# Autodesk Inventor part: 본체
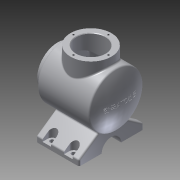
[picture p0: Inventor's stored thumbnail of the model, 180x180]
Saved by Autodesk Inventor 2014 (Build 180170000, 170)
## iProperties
Created: 2017-04
Part Number: 본체
Material: 알루미늄 6061
Document SubType Name: Modeling
Designer: user
Density: 2.71 g/cm^3
Appearance: 알루미늄 - 평지
Mass: 1669.39 g
Surface Area: 1069.84 cm^2
Volume: 616.012 cm^3
Author: user
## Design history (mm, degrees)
sketch "스케치1"
  geometry: L1 (-54, 0)-(54, 0); L2 (-54, 0)-(-54, 50); L3 (-54, 50)-(42.336, 50); A1 r 113 centre (-59, 0) between (54, 0) and (42.336, 50); 2 further points
  constraints: 6 end point, 2 perpendicular, 2 point on circle, 1 centre point, 1 coincident, 1 horizontal, 1 horizontal alignment, 1 midpoint
  dimensions: "d1" = 113 radius of A1; "d2" = 108 distance from line of L1.end L2; "d3" = 100 diameter of L3 L1
revolve "회전1" sketch "스케치1" stored, may be unused: angle "d4" = 90 deg
sketch "스케치2"
  geometry: C1 r 50 at (0, 0) reference; C2 r 38 at (0, 0)
  constraints: 1 centre point, 1 coincident
  dimensions: "d5" = 76 diameter of C2
extrude "돌출1" join sketch "스케치2" distance "d6" = 12; taper "d7" = 0 deg
node "작업 평면1"
sketch "스케치3"
  geometry: L1 (-45.101, 21.584)-(-72, 60); L2 (-72, 60)-(-82, 60); L3 (-82, 60)-(-82, -60); L4 (-82, -60)-(-72, -60); L5 (-72, -60)-(-45.101, -21.584); A1 r 50 centre (0, 0) between (-45.101, 21.584) and (-45.101, -21.584) reference; A2 r 18 centre (-82, 0) between (-82, -18) and (-82, 18); 2 further points
  constraints: 10 end point, 4 point on circle, 2 perpendicular, 2 point on line, 1 centre point, 1 coincident, 1 horizontal, 1 horizontal alignment, 1 midpoint
  dimensions: "d9" = 82 distance from line of point (0, 0) L3; "d10" = 10 distance of L1.end L2.end; "d11" = 10 distance of L3.end L4.end; "d12" = 55 deg angle of L1 L2; "d13" = 55 deg angle of L5 L4; "d14" = 120 distance of L2.end L3.end; "d15" = 36 diameter of A2
extrude "돌출2" join sketch "스케치3" distance "d16" = 80; taper "d17" = 0 deg
node "작업 평면2"
sketch "스케치4"
  geometry: L1 (-8, 10)-(-8, 110) reference; C1 r 38 at (42, 60); 1 further point
  constraints: 1 centre point, 1 horizontal alignment
  dimensions: "d19" = 76 diameter of C1; "d20" = 50 distance from line of C1.centre L1
extrude "돌출3" join sketch "스케치4" stored distance "d21" = 80; taper "d22" = 0 deg
sketch "스케치5"
  geometry: L1 (66, -38)-(66, 38) reference; L2 (66, 0)-(-54, 0); L3 (54, 50)-(-42.336, 50) reference; L4 (54, 50)-(54, -50) reference; L5 (54, 38)-(66, 38) reference; L6 (54, -38)-(66, -38) reference; L7 (54, -50)-(-42.336, -50) reference; L8 (-33.903, 40)-(41, 40); L9 (44, 37)-(44, 27); L10 (44, 27)-(66, 27); A1 r 113 centre (59, 0) between (-42.336, 50) and (-42.336, -50) reference; A2 r 103 centre (59, 0) between (-36.69, 38.11) and (-44, 0); A3 r 3 centre (-33.903, 37) between (-33.903, 40) and (-36.69, 38.11); A4 r 3 centre (41, 37) between (44, 37) and (41, 40); 2 further points
  constraints: 8 end point, 8 point on circle, 4 tangent, 3 centre point, 3 point on line, 1 equal radius, 1 midpoint, 1 perpendicular
  dimensions: "d23" = 10 radial gap between concentric circles of A2 A1; "d24" = 10 distance between parallel lines of L8 L3; "d25" = 80 diameter of L8 L2 (derived); "d26" = 10 distance between parallel lines of L9 L4; "d27" = 54 diameter of L10 L2; "d28" = 3 radius of A3; "d44" = 22 distance of L9.end L10.end (derived)
revolve "회전2" sketch "스케치5" stored, may be unused: angle "d29" = 90 deg
sketch "스케치6"
  geometry: C1 r 38 at (0, 0) reference; C2 r 27 at (0, 0); 1 further point
  constraints: 1 centre point, 1 coincident
  dimensions: "d30" = 54 diameter of C2
extrude "돌출4" cut sketch "스케치6" stored distance "d31" = 80; taper "d32" = 0 deg
sketch "스케치7"
  geometry: C1 r 27 at (0, 0) reference; C2 r 38 at (0, 0) reference; A1 r 32.5 centre (0, 0) between (0, 32.5) and (-32.5, 0); 3 further points
  constraints: 4 point on circle, 2 horizontal alignment, 2 vertical alignment, 1 centre point, 1 coincident
  dimensions: "d33" = 65 diameter of A1
hole "구멍1" sketch "스케치7" at (0, 32.5), (-32.5, 0), (32.5, 0), (0, -32.5) diameter "d34" = 3.242; stored, may be unused: countersink angle "d38" = 90 deg, drill point angle "d40" = 118 deg; dims "d35" = 8, "d36" = 4, "d37" = 2, "d39" = 10
chamfer "모따기1" distance "d41" = 1; stored, may be unused: second distance "d42" = 2, angle "d43" = 45 deg
sketch "스케치8"
  geometry: C1 r 38 at (0, 0) reference; C2 r 28 at (0, 0) reference; A1 r 32.5 centre (0, 0) between (0, 32.5) and (32.5, 0); 2 further points
  constraints: 4 point on circle, 2 horizontal alignment, 2 vertical alignment, 1 centre point, 1 coincident
  dimensions: "d45" = 65 diameter of A1
hole "구멍2" sketch "스케치8" at (0, 32.5), (32.5, 0), (0, -32.5), (-32.5, 0) diameter "d46" = 3.242; stored, may be unused: countersink angle "d50" = 90 deg, drill point angle "d52" = 118 deg; dims "d47" = 8, "d48" = 4, "d49" = 2, "d51" = 10
node "작업 평면3"
sketch "스케치9"
  geometry: L1 (80, 0)-(80, 42) reference; L2 (0, 0)-(80, 0) reference; L3 (12, 10)-(12, 0); L4 (28, 10)-(28, 0); L5 (52, 10)-(52, 0); L6 (68, 10)-(68, 0); A1 r 8 centre (60, 10) between (68, 10) and (52, 10); A2 r 8 centre (20, 10) between (28, 10) and (12, 10); 1 further point
  constraints: 8 end point, 4 point on circle, 4 point on line, 4 tangent, 3 perpendicular, 2 centre point, 1 horizontal alignment, 1 parallel
  dimensions: "d54" = 16 diameter of A1; "d55" = 16 diameter of A2; "d56" = 40 distance of A1.centre A2.centre; "d57" = 20 distance from line of A1.centre L1; "d58" = 10 distance from line of A1.centre L2
extrude "돌출5" cut sketch "스케치9" stored distance "d59" = 80; taper "d60" = 0 deg
hole "구멍3" diameter "d63" = 8; stored, may be unused: countersink angle "d67" = 90 deg, drill point angle "d69" = 118 deg; dims "d61" = 10, "d62" = 10, "d64" = 8, "d65" = 4, "d66" = 2, "d68" = 10
hole "구멍4" diameter "d72" = 8; stored, may be unused: countersink angle "d76" = 90 deg, drill point angle "d78" = 118 deg; dims "d70" = 10, "d71" = 10, "d73" = 8, "d74" = 4, "d75" = 2, "d77" = 10
node "작업 평면4"
sketch "스케치10"
  geometry: 2 further points
  constraints: 1 coincident, 1 other
feature "엠보싱1" sketch "스케치10" dims "d1" = 113, "d2" = 108, "d3" = 100, "d79" = 0.5, "d80" = 0
chamfer "모따기2" distance "d81" = 1; stored, may be unused: second distance "d82" = 2, angle "d83" = 45 deg
fillet "모깎기1" dims "d84" = 3
fillet "모깎기2" dims "d85" = 3
fillet "모깎기3" dims "d86" = 3
fillet "모깎기4" dims "d87" = 3
fillet "모깎기5" dims "d88" = 3
fillet "모깎기6" dims "d89" = 3
node "솔리드1"
mirror "대칭1"
mirror "대칭2"
other parameters: "d8" = -8, "d18" = -147, "d53" = -6
